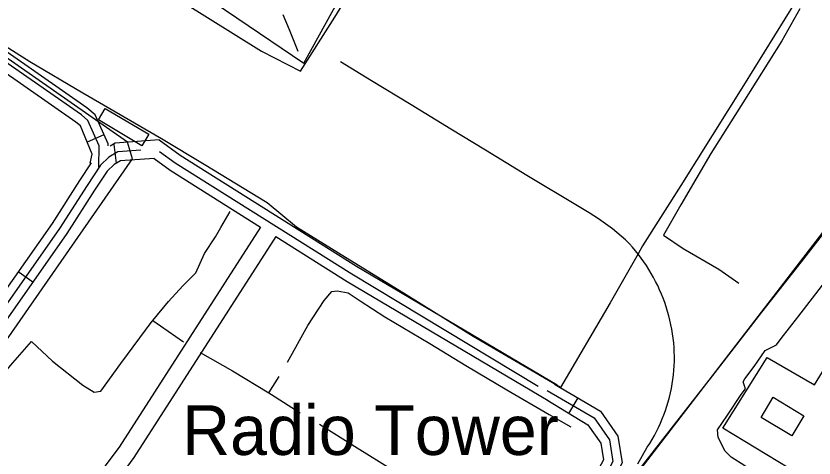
# Model space of a CAD drawing. Extents: x 3329332 to 3367211, y 631066 to 656469.
# Drawn here: x 3349570 to 3350903, y 646097 to 646835 of the extents above; entities that cross this region are included whole.
import ezdxf

# ---------------------------------------------------------------- set-up
doc = ezdxf.new("R2010")
doc.units = 0
for name, color, linetype in [('V-BLDG-OTLN', 7, 'Continuous'), ('V-RAIL-TRAK', 7, 'Continuous'), ('V-ROAD-CNTR', 7, 'Continuous'), ('V-SITE-OTLN', 7, 'Continuous'), ('V-TOPO-SHOR', 7, 'Continuous'), ('V-TOPO-TOWR-IDEN', 7, 'Continuous')]:
    doc.layers.add(name, color=color, linetype=linetype)

msp = doc.modelspace()

# ---------------------------------------------------------------- linework, layer by layer
at = {"layer": 'V-BLDG-OTLN'}
for points in [[(3349719.5, 646680.6), (3349792, 646637.4), (3349780.6, 646618.3), (3349708.1, 646661.4)], [(3350834.8, 646198.2), (3350886, 646167.2), (3350865.8, 646133.7), (3350814.6, 646164.6)]]:
    msp.add_lwpolyline(points, close=True, dxfattribs=at)
at = {"layer": 'V-RAIL-TRAK'}
for points in [[(3350668.8, 646289), (3350667.9, 646296.6), (3350666.8, 646304.2), (3350665.5, 646311.8), (3350664.1, 646319.3), (3350662.4, 646326.8), (3350660.5, 646334.3), (3350658.4, 646341.6), (3350656.2, 646349), (3350653.7, 646356.3), (3350651.1, 646363.5), (3350648.2, 646370.6), (3350645.2, 646377.6), (3350642, 646384.6), (3350638.6, 646391.5), (3350635, 646398.3), (3350631.2, 646405), (3350627.3, 646411.6), (3350623.2, 646418), (3350618.9, 646424.4), (3350614.5, 646430.7), (3350609.9, 646436.8), (3350605.1, 646442.8), (3350600.2, 646448.7), (3350595.1, 646454.4), (3350588.1, 646460.9), (3350581, 646467.2), (3350573.7, 646473.3), (3350566.3, 646479.3), (3350558.8, 646485.1), (3350551.2, 646490.7), (3350543.4, 646496.1), (3350535.4, 646501.3), (3350527.4, 646506.4), (3350519.3, 646511.3), (3350511, 646515.9), (3350423.6, 646568.7), (3350354.4, 646610.6), (3350296.7, 646646.1), (3350230.1, 646686.6), (3350164.1, 646726.5), (3350112.6, 646758.3)], [(3350083.2, 645396.8), (3350129.1, 645456.5), (3350181.5, 645522.9), (3350225.4, 645578.2), (3350256.8, 645620.1), (3350263.2, 645628.4), (3350272.3, 645640.2), (3350340, 645727.4), (3350390.2, 645792.2), (3350423.4, 645835.3), (3350429.1, 645842.7), (3350476.3, 645901.4), (3350556.9, 646005.6), (3350618.6, 646087.1), (3350664.5, 646145.2), (3350737.8, 646239.4), (3350816, 646340), (3350882.1, 646424.3), (3350960, 646524.6), (3351030.3, 646616), (3351065, 646661)], [(3350608.8, 646086.8), (3350616.8, 646100.7), (3350624.6, 646114.8), (3350628.7, 646121.2), (3350632.7, 646127.7), (3350636.5, 646134.4), (3350640, 646141.1), (3350643.4, 646147.9), (3350646.6, 646154.9), (3350649.6, 646161.9), (3350652.4, 646169), (3350655, 646176.2), (3350657.4, 646183.4), (3350659.6, 646190.7), (3350661.6, 646198.1), (3350663.3, 646205.5), (3350664.9, 646213), (3350666.3, 646220.5), (3350667.4, 646228.1), (3350668.3, 646235.7), (3350669, 646243.3), (3350669.5, 646250.9), (3350669.8, 646258.5), (3350669.9, 646266.1), (3350669.7, 646273.8), (3350669.3, 646281.4), (3350668.8, 646289)]]:
    msp.add_lwpolyline(points, dxfattribs=at)
at = {"layer": 'V-ROAD-CNTR'}
for p, q in [((3349690.1, 646624.8), (3349717.5, 646637.1)), ((3349738.1, 646589.1), (3349734.1, 646620.4)), ((3349598.5, 646390.5), (3349574, 646407.7)), ((3350508.4, 646197.2), (3350493.2, 646171.3))]:
    msp.add_line(p, q, dxfattribs=at)
for points in [[(3349709, 646582.2), (3349709.6, 646618.1), (3349690.6, 646660.5), (3349679.8, 646669.6), (3349511, 646786.9), (3349421.2, 646863.1), (3349281.7, 646971), (3349195.9, 647041.7), (3349137.8, 647087.9)], [(3349724.6, 646618.3), (3349724.6, 646621.2), (3349702.9, 646669.8), (3349688.9, 646681.5), (3349520.2, 646798.8), (3349430.7, 646874.7), (3349291.1, 646982.7), (3349205.3, 647053.3), (3349161.5, 647088.2)], [(3349694.1, 646589.2), (3349697.4, 646604.1), (3349678.3, 646651.2), (3349670.6, 646657.6), (3349501.9, 646775), (3349411.8, 646851.4), (3349272.3, 646959.3), (3349186.5, 647030), (3349141.7, 647065.7)], [(3351124.8, 646726.9), (3351014.2, 646599), (3350539.1, 645982.1), (3350195.8, 645554.3), (3349987.2, 645280.3)], [(3349809.4, 646628.1), (3349735.8, 646622.6), (3349727.5, 646617.7)], [(3349809.4, 646628.1), (3349844.8, 646602.3), (3350139, 646417.1), (3350474.3, 646218.7)], [(3349778.8, 646610.9), (3349740.4, 646607.9), (3349725.2, 646599), (3349711.3, 646585.7), (3349689.2, 646552), (3349643.1, 646479.8), (3349508.9, 646289.2), (3349395.6, 646133.9), (3349288.7, 645987.8), (3349240, 645921), (3349147.6, 645798.4), (3349105.2, 645753.1), (3349070.4, 645734.6), (3349032, 645723.8), (3348964.9, 645726.9), (3348919.8, 645716.5), (3348901.4, 645705.8), (3348871.6, 645677.8), (3348864.1, 645643.7), (3348844, 645597), (3348803.6, 645538.9), (3348766.1, 645496.1), (3348720.5, 645447.2), (3348699.5, 645414.7)], [(3349810.3, 646608.8), (3349836.4, 646589.8), (3350131.1, 646404.4), (3350442.4, 646216.5)], [(3349801, 646597.1), (3349745, 646593.2), (3349734.3, 646586.9), (3349722.9, 646576), (3349701.8, 646543.8), (3349655.5, 646471.4), (3349521.1, 646280.5), (3349407.7, 646125), (3349300.8, 645978.9), (3349283.1, 645954.7)], [(3349801, 646597.1), (3349828, 646577.4), (3349978.9, 646482.4)], [(3349696, 646589.7), (3349676.6, 646560.1), (3349630.6, 646488.1), (3349496.7, 646298), (3349383.5, 646142.7), (3349276.6, 645996.6), (3349254, 645965.7)], [(3349978.9, 646482.4), (3349742.7, 646114.6), (3349661.9, 646007.4), (3349611.3, 645936.2)], [(3350004.3, 646466.4), (3349767.3, 646097.5), (3349754.9, 646080.9)], [(3350004.3, 646466.4), (3350123.2, 646391.6), (3350459, 646192.7)], [(3350457.7, 646209.6), (3350536.1, 646163.6), (3350561.5, 646127.3), (3350567.1, 646091.1), (3350545.1, 646050.5), (3350409.9, 645869.6), (3350359.2, 645801.1), (3350284.3, 645734.9), (3350231.8, 645693.2)], [(3350469.7, 646220.1), (3350546.5, 646174.9), (3350575.7, 646133), (3350582.7, 646088.4), (3350557.7, 646042.4), (3350421.9, 645860.6), (3350370.3, 645790.9), (3350293.9, 645723.4), (3350251.9, 645690)], [(3350456.7, 646193.9), (3350525.6, 646152.3), (3350547.2, 646121.5), (3350551.5, 646093.8), (3350532.4, 646058.6), (3350397.9, 645878.5), (3350348.1, 645811.3), (3350274.6, 645746.4), (3350231.8, 645712.4)]]:
    msp.add_lwpolyline(points, dxfattribs=at)
at = {"layer": 'V-SITE-OTLN'}
for points in [[(3349641.2, 647033.8), (3350051, 646756.3), (3350596.6, 647743.4)], [(3349804.3, 646886.1), (3349980.6, 646776.1), (3350045.7, 646742.8), (3350103, 646832.9), (3350208.3, 647004.1)], [(3350871.3, 646858.2), (3350785.5, 646719), (3350680.9, 646551.9), (3350616.5, 646450.9), (3350609.2, 646437.6), (3350562.6, 646355.6), (3350479.7, 646214.6), (3350333.6, 646299.9), (3350221.8, 646369.1), (3350108.8, 646438.9), (3350038.7, 646482), (3349989.8, 646523.1), (3349884.8, 646587), (3349813.5, 646629.6), (3349682.2, 646706), (3349593.8, 646758.1), (3349500.2, 646817.2)], [(3349279, 645897.6), (3349765.2, 646596.4), (3349756.5, 646623.9), (3349479.4, 646817.1)]]:
    msp.add_lwpolyline(points, dxfattribs=at)
msp.add_lwpolyline([(3351330.6, 645896.7), (3351242.7, 645949.9), (3351095.6, 646041.5), (3351044.1, 646067.1), (3350996.9, 645995.3), (3350930.7, 646036.1), (3350861.2, 646079.8), (3350750.5, 646146.7), (3350824.9, 646264.7), (3350903.7, 646219.1), (3350939.2, 646277), (3351018.4, 646406.5), (3351113.1, 646560.5), (3351150.3, 646621), (3351324.3, 646515.1), (3351459.5, 646431.1), (3351606.7, 646344.1), (3351526.3, 646214.6), (3351430.5, 646057.2)], close=True, dxfattribs=at)
at = {"layer": 'V-TOPO-SHOR'}
for p, q in [((3349798.7, 646326.2), (3349850.4, 646290.6)), ((3349992.7, 646205.4), (3350010, 646232.9))]:
    msp.add_line(p, q, dxfattribs=at)
for points in [[(3350041.8, 646775.8), (3350027.1, 646811.7), (3350016.6, 646836.7)], [(3350879.4, 646846.6), (3350849.2, 646793.5), (3350784.4, 646690), (3350730.8, 646605.4), (3350680.4, 646519.5), (3350651.5, 646469), (3350684.3, 646446.8), (3350744.3, 646412), (3350777.7, 646388.5)], [(3349320.4, 645933.3), (3349349.8, 645976.8), (3349392.1, 646035.1), (3349440.3, 646099.3), (3349500.6, 646177.8), (3349561, 646251.1), (3349596.4, 646291.3), (3349631.3, 646258.6), (3349682, 646218.5), (3349701.2, 646206.4), (3349712.1, 646208.5), (3349745.6, 646254.8), (3349797.8, 646325.1), (3349798.7, 646326.2), (3349825.1, 646358.1), (3349848.8, 646384.2), (3349870.8, 646406.2), (3349885.3, 646438.1), (3349903.6, 646465.9), (3349912.5, 646481.7), (3349928.2, 646508.5)], [(3350600.1, 645754.3), (3350696.4, 645876.5), (3350791.4, 645997.4), (3350788.9, 646003.8), (3350765.6, 646018.2), (3350761.3, 646026.5), (3350781.4, 646053), (3350795.8, 646077), (3350787.7, 646083.5), (3350764.9, 646097.9), (3350754.9, 646108.2), (3350743.2, 646130.8), (3350742.1, 646143.5), (3350758.4, 646168.1), (3350781.3, 646202.8), (3350788.4, 646212.3), (3350784.8, 646223.8), (3350787.4, 646228.9), (3350803.1, 646249.7), (3350821.3, 646276.1), (3350840.6, 646286), (3350848.4, 646296.1), (3350875.8, 646332), (3350941.5, 646417)], [(3350023.8, 646256.5), (3350057.6, 646318.2), (3350085, 646359.8), (3350098, 646374.6), (3350107, 646376), (3350125.4, 646372.6), (3350145, 646359.2), (3350186.6, 646332.7), (3350261.5, 646288.1), (3350321.4, 646251.2), (3350390.3, 646210.5), (3350460.7, 646169.3), (3350497.1, 646148.9)], [(3349878.1, 646272.9), (3349932.2, 646242.4), (3349992.7, 646205.4), (3349996.9, 646202.8), (3350044.9, 646172.1)], [(3350077.4, 646153.4), (3350140.2, 646113.5), (3350197.3, 646078.2), (3350235.2, 646055.9), (3350279.1, 646028.4), (3350308.1, 646010.4), (3350287.2, 645977.6), (3350234.2, 645912.2), (3350190.9, 645856.1), (3350152.9, 645811.8)]]:
    msp.add_lwpolyline(points, dxfattribs=at)

# ---------------------------------------------------------------- texts
at = {"layer": 'V-TOPO-TOWR-IDEN'}
msp.add_text('Radio Tower', height=83, dxfattribs=at).set_placement((3349847.8, 646101.8))

doc.saveas('drawing.dxf')
